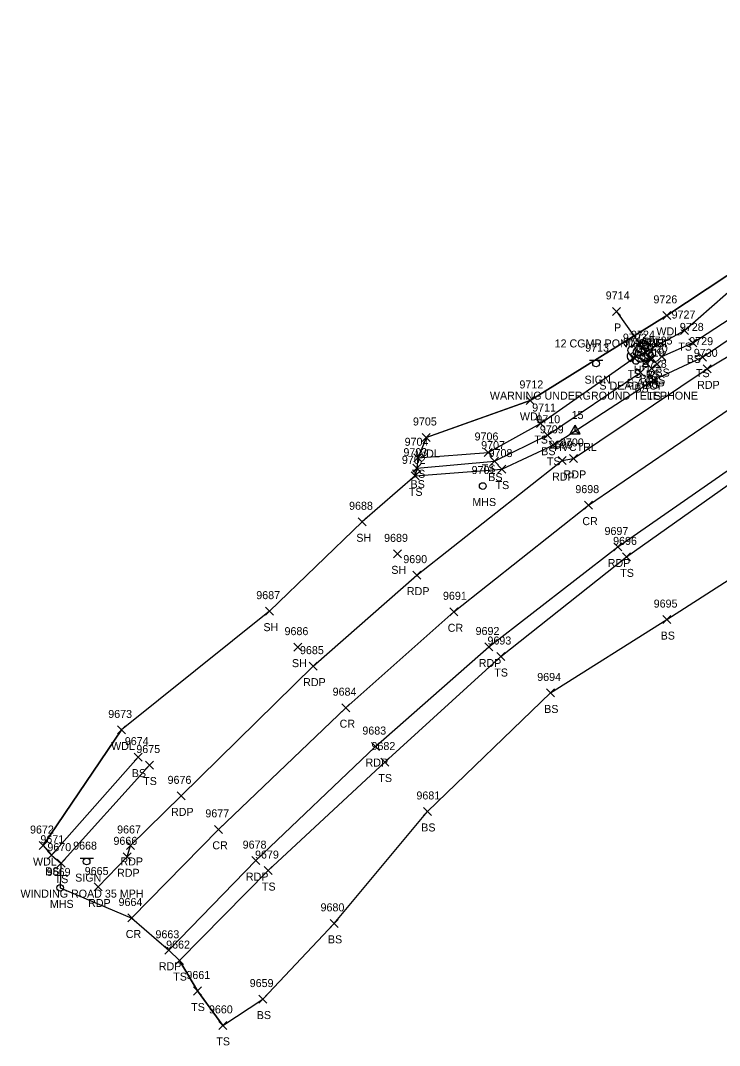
# Model space of a CAD drawing. Extents: x 1651685 to 1653558, y 889533 to 891085.
# Drawn here: x 1651685 to 1651859.6, y 889532.8 to 889789.1 of the extents above; entities that cross this region are included whole.
import ezdxf

# ---------------------------------------------------------------- set-up
doc = ezdxf.new("R2010")
doc.units = 0
for name, color, linetype in [('C_A', 7, 'Continuous'), ('C_I', 7, 'Continuous'), ('CPSM', 7, 'Continuous'), ('D_A', 7, 'Continuous'), ('D_C', 7, 'Continuous'), ('D_I', 7, 'Continuous'), ('D_TIC', 7, 'Continuous'), ('DCP', 7, 'Continuous'), ('L_A', 7, 'Continuous'), ('L_C', 7, 'Continuous'), ('L_I', 7, 'Continuous'), ('L_TIC', 7, 'Continuous'), ('LAWA', 7, 'Continuous'), ('LELB', 7, 'Continuous'), ('LSOGP', 7, 'Continuous'), ('LTD', 7, 'Continuous'), ('P_A', 7, 'Continuous'), ('P_I', 7, 'Continuous'), ('P_TIC', 7, 'Continuous'), ('PET', 7, 'Continuous'), ('PRC', 7, 'Continuous'), ('S_A', 7, 'Continuous'), ('S_C', 7, 'Continuous'), ('S_I', 7, 'Continuous'), ('SSGN', 7, 'Continuous'), ('U_A', 7, 'Continuous'), ('U_I', 7, 'Continuous'), ('USMH', 7, 'Continuous')]:
    doc.layers.add(name, color=color, linetype=linetype)

msp = doc.modelspace()

# ---------------------------------------------------------------- linework, layer by layer
at = {"layer": 'CPSM'}
for p, q in [((1651822.33, 889685.73), (1651823.58, 889687.9)), ((1651824.83, 889685.73), (1651823.58, 889687.9)), ((1651823.58, 889686.45), (1651823.58, 889687.9)), ((1651822.33, 889685.73), (1651823.58, 889686.45)), ((1651822.33, 889685.73), (1651824.83, 889685.73)), ((1651823.58, 889686.45), (1651823.58, 889686.45)), ((1651823.58, 889686.45), (1651824.83, 889685.73))]:
    msp.add_line(p, q, dxfattribs=at)
at = {"layer": 'D_TIC'}
for points in [[(1651832.89, 889715.33), (1651834.89, 889717.33)], [(1651834.89, 889715.33), (1651832.89, 889717.33)], [(1651841.32, 889703.45), (1651843.32, 889705.45)], [(1651843.32, 889703.45), (1651841.32, 889705.45)]]:
    msp.add_lwpolyline(points, dxfattribs=at)
at = {"layer": 'DCP'}
msp.add_lwpolyline([(1651833.89, 889716.33), (1651842.32, 889704.45)], dxfattribs=at)
at = {"layer": 'L_TIC'}
for points in [[(1651845.44, 889714.35), (1651847.44, 889716.35)], [(1651847.44, 889714.35), (1651845.44, 889716.35)], [(1651849.92, 889710.55), (1651851.92, 889712.55)], [(1651851.92, 889710.55), (1651849.92, 889712.55)], [(1651851.98, 889707.46), (1651853.98, 889709.46)], [(1651853.98, 889707.46), (1651851.98, 889709.46)], [(1651837.28, 889703.72), (1651839.28, 889705.72)], [(1651839.28, 889703.72), (1651837.28, 889705.72)], [(1651841.79, 889703.58), (1651843.79, 889705.58)], [(1651843.79, 889703.58), (1651841.79, 889705.58)], [(1651844.19, 889704.05), (1651846.19, 889706.05)], [(1651846.19, 889704.05), (1651844.19, 889706.05)], [(1651854.35, 889703.9), (1651856.35, 889705.9)], [(1651856.35, 889703.9), (1651854.35, 889705.9)], [(1651840.26, 889702.55), (1651842.26, 889704.55)], [(1651842.26, 889702.55), (1651840.26, 889704.55)], [(1651840.26, 889702.55), (1651842.26, 889704.55)], [(1651842.26, 889702.55), (1651840.26, 889704.55)], [(1651841.6, 889701.06), (1651843.6, 889703.06)], [(1651843.6, 889701.06), (1651841.6, 889703.06)], [(1651841.6, 889701.06), (1651843.6, 889703.06)], [(1651843.6, 889701.06), (1651841.6, 889703.06)], [(1651843.08, 889702.13), (1651845.08, 889704.13)], [(1651845.08, 889702.13), (1651843.08, 889704.13)], [(1651838.92, 889700.07), (1651840.92, 889702.07)], [(1651840.92, 889700.07), (1651838.92, 889702.07)], [(1651842.19, 889698.23), (1651844.19, 889700.23)], [(1651844.19, 889698.23), (1651842.19, 889700.23)], [(1651811.33, 889693.08), (1651813.33, 889695.08)], [(1651813.33, 889693.08), (1651811.33, 889695.08)], [(1651813.94, 889687.3), (1651815.94, 889689.3)], [(1651815.94, 889687.3), (1651813.94, 889689.3)], [(1651785.37, 889683.82), (1651787.37, 889685.82)], [(1651787.37, 889683.82), (1651785.37, 889685.82)], [(1651815.65, 889684.38), (1651817.65, 889686.38)], [(1651817.65, 889684.38), (1651815.65, 889686.38)], [(1651800.82, 889680.07), (1651802.82, 889682.07)], [(1651802.82, 889680.07), (1651800.82, 889682.07)], [(1651817.09, 889681.86), (1651819.09, 889683.86)], [(1651819.09, 889681.86), (1651817.09, 889683.86)], [(1651783.29, 889678.75), (1651785.29, 889680.75)], [(1651785.29, 889678.75), (1651783.29, 889680.75)], [(1651802.41, 889677.92), (1651804.41, 889679.92)], [(1651804.41, 889677.92), (1651802.41, 889679.92)], [(1651782.99, 889676.15), (1651784.99, 889678.15)], [(1651784.99, 889676.15), (1651782.99, 889678.15)], [(1651804.26, 889675.92), (1651806.26, 889677.92)], [(1651806.26, 889675.92), (1651804.26, 889677.92)], [(1651782.6, 889674.23), (1651784.6, 889676.23)], [(1651784.6, 889674.23), (1651782.6, 889676.23)], [(1651769.38, 889662.75), (1651771.38, 889664.75)], [(1651771.38, 889662.75), (1651769.38, 889664.75)], [(1651778.14, 889654.73), (1651780.14, 889656.73)], [(1651780.14, 889654.73), (1651778.14, 889656.73)], [(1651835.41, 889653.97), (1651837.41, 889655.97)], [(1651837.41, 889653.97), (1651835.41, 889655.97)], [(1651746.19, 889640.41), (1651748.19, 889642.41)], [(1651748.19, 889640.41), (1651746.19, 889642.41)], [(1651845.48, 889638.3), (1651847.48, 889640.3)], [(1651847.48, 889638.3), (1651845.48, 889640.3)], [(1651753.3, 889631.41), (1651755.3, 889633.41)], [(1651755.3, 889631.41), (1651753.3, 889633.41)], [(1651803.95, 889629.07), (1651805.95, 889631.07)], [(1651805.95, 889629.07), (1651803.95, 889631.07)], [(1651816.38, 889619.96), (1651818.38, 889621.96)], [(1651818.38, 889619.96), (1651816.38, 889621.96)], [(1651709.2, 889610.71), (1651711.2, 889612.71)], [(1651711.2, 889610.71), (1651709.2, 889612.71)], [(1651713.33, 889603.92), (1651715.33, 889605.92)], [(1651715.33, 889603.92), (1651713.33, 889605.92)], [(1651716.21, 889601.94), (1651718.21, 889603.94)], [(1651718.21, 889601.94), (1651716.21, 889603.94)], [(1651774.98, 889602.69), (1651776.98, 889604.69)], [(1651776.98, 889602.69), (1651774.98, 889604.69)], [(1651785.64, 889590.34), (1651787.64, 889592.34)], [(1651787.64, 889590.34), (1651785.64, 889592.34)], [(1651689.66, 889581.82), (1651691.66, 889583.82)], [(1651691.66, 889581.82), (1651689.66, 889583.82)], [(1651691.68, 889579.4), (1651693.68, 889581.4)], [(1651693.68, 889579.4), (1651691.68, 889581.4)], [(1651694.09, 889577.42), (1651696.09, 889579.42)], [(1651696.09, 889577.42), (1651694.09, 889579.42)], [(1651745.88, 889575.56), (1651747.88, 889577.56)], [(1651747.88, 889575.56), (1651745.88, 889577.56)], [(1651762.34, 889562.37), (1651764.34, 889564.37)], [(1651764.34, 889562.37), (1651762.34, 889564.37)], [(1651723.72, 889553.06), (1651725.72, 889555.06)], [(1651725.72, 889553.06), (1651723.72, 889555.06)], [(1651728.21, 889545.46), (1651730.21, 889547.46)], [(1651730.21, 889545.46), (1651728.21, 889547.46)], [(1651744.55, 889543.44), (1651746.55, 889545.44)], [(1651746.55, 889543.44), (1651744.55, 889545.44)], [(1651734.5, 889536.87), (1651736.5, 889538.87)], [(1651736.5, 889536.87), (1651734.5, 889538.87)]]:
    msp.add_lwpolyline(points, dxfattribs=at)
at = {"layer": 'LAWA'}
for points in [[(1651786.37, 889684.82), (1651812.33, 889694.08), (1651846.44, 889715.35), (1651881.58, 889738.54), (1651911.24, 889756.58), (1651953.91, 889775.98), (1651985.79, 889786.86)], [(1651690.66, 889582.82), (1651710.2, 889611.71)]]:
    msp.add_lwpolyline(points, dxfattribs=at)
at = {"layer": 'LELB'}
for points in [[(1651783.6, 889675.23), (1651805.26, 889676.92), (1651818.09, 889682.86), (1651843.19, 889699.23), (1651855.35, 889704.9), (1651888.23, 889726.95), (1651920.63, 889744.86), (1651960.2, 889763.86), (1651990.86, 889775.67), (1652032.94, 889794.22), (1652064, 889805.11), (1652064.62, 889808.53), (1652063.28, 889810.56), (1652051.23, 889809.28), (1652039.29, 889812.4)], [(1651845.19, 889705.05), (1651852.98, 889708.46), (1651886.2, 889730.12), (1651918.71, 889747.83), (1651956.73, 889770.8), (1651985.79, 889786.86), (1652029.06, 889802.11), (1652062.87, 889807.04)], [(1651784.29, 889679.75), (1651801.82, 889681.07), (1651814.94, 889688.3), (1651838.28, 889704.72), (1651850.92, 889711.55), (1651881.58, 889738.54)], [(1651842.6, 889702.06), (1651844.08, 889703.13), (1651842.79, 889704.58), (1651841.26, 889703.55)], [(1651842.6, 889702.06), (1651841.26, 889703.55)], [(1651783.99, 889677.15), (1651803.41, 889678.92), (1651816.65, 889685.38), (1651839.92, 889701.07)], [(1651735.5, 889537.87), (1651729.21, 889546.46), (1651724.72, 889554.06), (1651746.88, 889576.56), (1651775.98, 889603.69), (1651804.95, 889630.07), (1651836.41, 889654.97), (1651869.76, 889678.65), (1651890.05, 889689.78)], [(1651745.55, 889544.44), (1651763.34, 889563.37), (1651786.64, 889591.34), (1651817.38, 889620.96), (1651846.48, 889639.3)], [(1651692.68, 889580.4), (1651714.33, 889604.92)], [(1651695.09, 889578.42), (1651717.21, 889602.94)]]:
    msp.add_lwpolyline(points, dxfattribs=at)
at = {"layer": 'LSOGP'}
msp.add_lwpolyline([(1651881.58, 889738.53), (1651846.44, 889715.35), (1651812.33, 889694.08), (1651786.38, 889684.82), (1651784.29, 889679.75), (1651783.98, 889677.15), (1651783.6, 889675.23), (1651770.37, 889663.74), (1651747.19, 889641.41), (1651710.19, 889611.71), (1651690.66, 889582.82), (1651692.68, 889580.4), (1651695.08, 889578.42), (1651694.88, 889572.22), (1651712.82, 889564.7), (1651722.05, 889556.64), (1651724.72, 889554.06), (1651729.21, 889546.46), (1651735.5, 889537.87), (1651745.56, 889544.44), (1651763.33, 889563.37), (1651786.64, 889591.33), (1651817.38, 889620.96), (1651846.48, 889639.3), (1651872.04, 889655.76)], dxfattribs=at)
at = {"layer": 'LTD'}
for p, q in [((1651838.75, 889705.79), (1651838.75, 889705.79)), ((1651838.75, 889705.79), (1651838.75, 889705.79)), ((1651840.79, 889706.52), (1651840.79, 889706.52)), ((1651840.79, 889706.52), (1651840.79, 889706.52))]:
    msp.add_line(p, q, dxfattribs=at)
for centre in [(1651838.8, 889707.23), (1651840.84, 889707.95)]:
    msp.add_arc(centre, 1.05, 335.5272, 180.9563, dxfattribs=at)
for centre, major_axis, ratio, start_param, end_param in [((1651837.96, 889706.46), (1.21, -0.51), 0.895232, 1.570796, 4.712389), ((1651840, 889707.19), (1.21, -0.51), 0.895232, 1.570796, 4.712389), ((1651839.79, 889706.38), (-1.14, -0.48), 0.949671, 1.570796, 4.712389), ((1651840.58, 889706.98), (-0.208, -0.792), 0.645439, 3.141593, 6.283185), ((1651841.83, 889707.1), (-1.14, -0.48), 0.949671, 1.570796, 4.712389), ((1651837.67, 889705.08), (0.58, -1.04), 0.959034, 3.141593, 6.283185), ((1651838.29, 889705.04), (-0.625, -0.083), 0.423636, 0, 3.141593), ((1651838.54, 889706.25), (-0.208, -0.792), 0.645439, 3.141593, 6.283185), ((1651839.71, 889705.81), (0.58, -1.04), 0.959034, 3.141593, 6.283185), ((1651839.25, 889705.63), (-0.5, 0.667), 0.989748, 3.141593, 6.283185), ((1651839.75, 889704.96), (-1.09, 0.79), 0.841452, 1.570796, 4.712389), ((1651840.79, 889705.02), (0.26, 1.06), 0.942809, 1.570796, 4.712389), ((1651840.33, 889705.77), (-0.625, -0.083), 0.423636, 0, 3.141593), ((1651841.29, 889706.35), (-0.5, 0.667), 0.989748, 3.141593, 6.283185), ((1651841.79, 889705.69), (-1.09, 0.79), 0.841452, 1.570796, 4.712389), ((1651838.75, 889704.29), (0.26, 1.06), 0.942809, 1.570796, 4.712389)]:
    msp.add_ellipse(centre, major_axis=major_axis, ratio=ratio, start_param=start_param, end_param=end_param, dxfattribs=at)
at = {"layer": 'P_TIC'}
for points in [[(1651855.55, 889700.98), (1651857.55, 889702.98)], [(1651857.55, 889700.98), (1651855.55, 889702.98)], [(1651819.32, 889678.04), (1651821.32, 889680.04)], [(1651821.32, 889678.04), (1651819.32, 889680.04)], [(1651822.18, 889678.59), (1651824.18, 889680.59)], [(1651824.18, 889678.59), (1651822.18, 889680.59)], [(1651825.92, 889666.91), (1651827.92, 889668.91)], [(1651827.92, 889666.91), (1651825.92, 889668.91)], [(1651833.2, 889656.45), (1651835.2, 889658.45)], [(1651835.2, 889656.45), (1651833.2, 889658.45)], [(1651783.02, 889649.41), (1651785.02, 889651.41)], [(1651785.02, 889649.41), (1651783.02, 889651.41)], [(1651792.27, 889640.25), (1651794.27, 889642.25)], [(1651794.27, 889640.25), (1651792.27, 889642.25)], [(1651800.99, 889631.45), (1651802.99, 889633.45)], [(1651802.99, 889631.45), (1651800.99, 889633.45)], [(1651757.1, 889626.66), (1651759.1, 889628.66)], [(1651759.1, 889626.66), (1651757.1, 889628.66)], [(1651765.27, 889616.28), (1651767.27, 889618.28)], [(1651767.27, 889616.28), (1651765.27, 889618.28)], [(1651772.7, 889606.56), (1651774.7, 889608.56)], [(1651774.7, 889606.56), (1651772.7, 889608.56)], [(1651724.08, 889594.24), (1651726.08, 889596.24)], [(1651726.08, 889594.24), (1651724.08, 889596.24)], [(1651733.46, 889585.87), (1651735.46, 889587.87)], [(1651735.46, 889585.87), (1651733.46, 889587.87)], [(1651711.47, 889581.84), (1651713.47, 889583.84)], [(1651713.47, 889581.84), (1651711.47, 889583.84)], [(1651710.6, 889579), (1651712.6, 889581)], [(1651712.6, 889579), (1651710.6, 889581)], [(1651742.79, 889578.05), (1651744.79, 889580.05)], [(1651744.79, 889578.05), (1651742.79, 889580.05)], [(1651703.37, 889571.46), (1651705.37, 889573.46)], [(1651705.37, 889571.46), (1651703.37, 889573.46)], [(1651711.82, 889563.71), (1651713.82, 889565.71)], [(1651713.82, 889563.71), (1651711.82, 889565.71)], [(1651721.05, 889555.64), (1651723.05, 889557.64)], [(1651723.05, 889555.64), (1651721.05, 889557.64)]]:
    msp.add_lwpolyline(points, dxfattribs=at)
at = {"layer": 'PET'}
for points in [[(1651722.05, 889556.64), (1651743.79, 889579.05), (1651773.7, 889607.56), (1651801.99, 889632.45), (1651834.2, 889657.45), (1651868.37, 889681.24), (1651890.21, 889694.54), (1651910.42, 889705.67), (1651932.43, 889717.43), (1651971.73, 889735.64), (1652001.72, 889748.76), (1652035.56, 889763.08), (1652038.22, 889762.81), (1652052.59, 889768.76), (1652053.52, 889770.62), (1652076.54, 889779.88), (1652117.63, 889796.48), (1652147.54, 889808.21), (1652195.16, 889826.81), (1652233.48, 889842.54), (1652271.73, 889857.62), (1652310.07, 889873.86), (1652345.02, 889890.88)], [(1651704.37, 889572.46), (1651711.6, 889580), (1651712.47, 889582.84), (1651725.08, 889595.24), (1651758.1, 889627.66), (1651784.02, 889650.41), (1651820.32, 889679.04), (1651823.18, 889679.59), (1651856.55, 889701.98), (1651890.95, 889722.59), (1651906.13, 889732.21), (1651930.88, 889744.68), (1651940.4, 889747.37), (1651962.5, 889757.26), (1651993.09, 889770.39), (1652035.55, 889788.28)]]:
    msp.add_lwpolyline(points, dxfattribs=at)
at = {"layer": 'PRC'}
msp.add_lwpolyline([(1651712.82, 889564.71), (1651734.46, 889586.87), (1651766.27, 889617.28), (1651793.27, 889641.25), (1651826.92, 889667.91), (1651862.27, 889692.04), (1651896.77, 889712.72), (1651926.87, 889728.69), (1651966.67, 889747.09), (1651996.7, 889760.13), (1652040.05, 889778.15), (1652073.02, 889791.69), (1652113.32, 889807.56), (1652142.44, 889819.25), (1652190.37, 889838.24), (1652228.92, 889853.82), (1652266.92, 889869.48), (1652304.43, 889885.84), (1652339.13, 889902.36), (1652374.76, 889921.45)], dxfattribs=at)
at = {"layer": 'SSGN'}
for p, q in [((1651827.13, 889704.14), (1651830.46, 889704.14)), ((1651828.77, 889703.3), (1651828.77, 889703.3)), ((1651699.85, 889579.66), (1651703.18, 889579.66)), ((1651701.5, 889578.82), (1651701.5, 889578.82))]:
    msp.add_line(p, q, dxfattribs=at)
for centre in [(1651828.77, 889703.3), (1651701.5, 889578.82)]:
    msp.add_circle(centre, 0.833, dxfattribs=at)
at = {"layer": 'USMH'}
for p, q in [((1651800.46, 889672.69), (1651800.46, 889672.69)), ((1651801.29, 889672.69), (1651801.29, 889672.69)), ((1651694.88, 889572.23), (1651694.88, 889572.23)), ((1651695.72, 889572.23), (1651695.72, 889572.23))]:
    msp.add_line(p, q, dxfattribs=at)
for centre in [(1651800.46, 889672.69), (1651694.88, 889572.23)]:
    msp.add_circle(centre, 0.833, dxfattribs=at)

# ---------------------------------------------------------------- texts
at = {"layer": 'C_A'}
msp.add_text('HVCTRL', height=2, dxfattribs=at).set_placement((1651818.27, 889681.45))
at = {"layer": 'C_I'}
msp.add_text('15', height=2, dxfattribs=at).set_placement((1651822.68, 889689.45))
at = {"layer": 'D_A'}
for p in [(1651833.27, 889711.33), (1651841.7, 889699.45)]:
    msp.add_text('P', height=2, dxfattribs=at).set_placement(p)
at = {"layer": 'D_C'}
msp.add_text('12 CGMP POND INLET', height=2, dxfattribs=at).set_placement((1651818.43, 889707.33))
at = {"layer": 'D_I'}
for s, p in [('9714', (1651831.2, 889719.33)), ('9715', (1651839.63, 889707.45))]:
    msp.add_text(s, height=2, dxfattribs=at).set_placement(p)
at = {"layer": 'L_A'}
for s, p in [('WDL', (1651843.85, 889710.35)), ('TS', (1651849.33, 889706.55)), ('BS', (1651851.42, 889703.46)), ('H', (1651838.18, 889700.79)), ('H', (1651840.22, 889701.52)), ('TS', (1651836.69, 889699.72)), ('BS', (1651839.7, 889698.55)), ('BS', (1651839.7, 889698.55)), ('BS', (1651841.23, 889699.58)), ('BS', (1651842.52, 889698.13)), ('BS', (1651843.63, 889700.05)), ('TS', (1651853.76, 889699.9)), ('BS', (1651838.36, 889696.07)), ('BS', (1651841.04, 889697.06)), ('BS', (1651841.04, 889697.06)), ('TS', (1651841.6, 889694.23)), ('WDL', (1651809.75, 889689.08)), ('TS', (1651813.35, 889683.3)), ('WDL', (1651783.79, 889679.82)), ('BS', (1651815.09, 889680.38)), ('TS', (1651816.5, 889677.86)), ('TS', (1651782.7, 889674.75)), ('TS', (1651800.23, 889676.07)), ('BS', (1651782.43, 889672.15)), ('BS', (1651801.85, 889673.92)), ('TS', (1651782.01, 889670.23)), ('TS', (1651803.67, 889671.92)), ('SH', (1651768.87, 889658.75)), ('SH', (1651777.62, 889650.73)), ('TS', (1651834.82, 889649.97)), ('SH', (1651745.68, 889636.41)), ('BS', (1651844.92, 889634.3)), ('SH', (1651752.79, 889627.41)), ('TS', (1651803.36, 889625.07)), ('BS', (1651815.82, 889615.96)), ('WDL', (1651707.61, 889606.71)), ('BS', (1651712.77, 889599.92)), ('TS', (1651715.62, 889597.94)), ('TS', (1651774.39, 889598.69)), ('BS', (1651785.09, 889586.34)), ('WDL', (1651688.08, 889577.82)), ('BS', (1651691.12, 889575.4)), ('TS', (1651693.5, 889573.42)), ('TS', (1651745.29, 889571.56)), ('BS', (1651761.78, 889558.37)), ('TS', (1651723.13, 889549.06)), ('TS', (1651727.62, 889541.46)), ('BS', (1651744, 889539.44)), ('TS', (1651733.9, 889532.87))]:
    msp.add_text(s, height=2, dxfattribs=at).set_placement(p)
at = {"layer": 'L_C'}
for s, p in [('S DEAD POP', (1651829.61, 889696.79)), ('S ASH', (1651836.41, 889697.52))]:
    msp.add_text(s, height=2, dxfattribs=at).set_placement(p)
at = {"layer": 'L_I'}
for s, p in [('9726', (1651843.12, 889718.35)), ('9727', (1651847.66, 889714.55)), ('9728', (1651849.72, 889711.46)), ('9723', (1651835.49, 889708.79)), ('9724', (1651837.53, 889709.52)), ('9725', (1651841.93, 889708.05)), ('9716', (1651835.54, 889707.72)), ('9722', (1651838, 889706.55)), ('9722', (1651838, 889706.55)), ('9721', (1651840.1, 889707.58)), ('9720', (1651840.73, 889706.13)), ('9729', (1651852.08, 889707.9)), ('9717', (1651837.22, 889704.07)), ('9719', (1651839.9, 889705.06)), ('9719', (1651839.9, 889705.06)), ('9718', (1651840.49, 889702.23)), ('9712', (1651809.64, 889697.08)), ('9711', (1651812.82, 889691.3)), ('9705', (1651783.03, 889687.82)), ('9710', (1651813.87, 889688.38)), ('9709', (1651814.74, 889685.86)), ('9704', (1651780.95, 889682.75)), ('9706', (1651798.43, 889684.07)), ('9703', (1651780.65, 889680.15)), ('9707', (1651800.07, 889681.92)), ('9708', (1651801.93, 889679.92)), ('9702', (1651780.26, 889678.23)), ('9688', (1651767.07, 889666.75)), ('9689', (1651775.82, 889658.73)), ('9696', (1651833.05, 889657.97)), ('9687', (1651743.88, 889644.41)), ('9695', (1651843.18, 889642.3)), ('9686', (1651750.94, 889635.41)), ('9693', (1651801.65, 889633.07)), ('9694', (1651814.08, 889623.96)), ('9673', (1651706.89, 889614.71)), ('9674', (1651711.03, 889607.92)), ('9675', (1651713.91, 889605.94)), ('9682', (1651772.67, 889606.69)), ('9681', (1651783.9, 889594.34)), ('9672', (1651687.35, 889585.82)), ('9671', (1651689.94, 889583.4)), ('9670', (1651691.69, 889581.42)), ('9679', (1651743.57, 889579.56)), ('9680', (1651759.94, 889566.37)), ('9662', (1651721.36, 889557.06)), ('9661', (1651726.42, 889549.46)), ('9659', (1651742.24, 889547.44)), ('9660', (1651732.05, 889540.87))]:
    msp.add_text(s, height=2, dxfattribs=at).set_placement(p)
at = {"layer": 'P_A'}
for s, p in [('RDP', (1651854.04, 889696.98)), ('RDP', (1651817.81, 889674.04)), ('RDP', (1651820.67, 889674.59)), ('CR', (1651825.35, 889662.91)), ('RDP', (1651831.69, 889652.45)), ('RDP', (1651781.51, 889645.41)), ('CR', (1651791.71, 889636.25)), ('RDP', (1651799.47, 889627.45)), ('RDP', (1651755.59, 889622.66)), ('CR', (1651764.7, 889612.28)), ('RDP', (1651771.18, 889602.56)), ('RDP', (1651722.57, 889590.24)), ('CR', (1651732.9, 889581.87)), ('RDP', (1651709.95, 889577.84)), ('RDP', (1651709.09, 889575)), ('RDP', (1651741.28, 889574.05)), ('RDP', (1651701.85, 889567.46)), ('CR', (1651711.26, 889559.71)), ('RDP', (1651719.53, 889551.64))]:
    msp.add_text(s, height=2, dxfattribs=at).set_placement(p)
at = {"layer": 'P_I'}
for s, p in [('9730', (1651853.21, 889704.98)), ('9700', (1651819.76, 889682.59)), ('9699', (1651817.01, 889682.04)), ('9698', (1651823.61, 889670.91)), ('9697', (1651830.9, 889660.45)), ('9690', (1651780.62, 889653.41)), ('9691', (1651790.53, 889644.25)), ('9692', (1651798.68, 889635.45)), ('9685', (1651754.8, 889630.66)), ('9684', (1651762.96, 889620.28)), ('9683', (1651770.39, 889610.56)), ('9676', (1651721.72, 889598.24)), ('9677', (1651731.16, 889589.87)), ('9667', (1651709.11, 889585.84)), ('9666', (1651708.19, 889583)), ('9678', (1651740.48, 889582.05)), ('9665', (1651701.01, 889575.46)), ('9664', (1651709.47, 889567.71)), ('9663', (1651718.69, 889559.64))]:
    msp.add_text(s, height=2, dxfattribs=at).set_placement(p)
at = {"layer": 'S_A'}
for p in [(1651825.91, 889698.28), (1651698.63, 889573.8)]:
    msp.add_text('SIGN', height=2, dxfattribs=at).set_placement(p)
at = {"layer": 'S_C'}
for s, p in [('WARNING UNDERGROUND TELEPHONE', (1651802.25, 889694.28)), ('WINDING ROAD 35 MPH', (1651684.96, 889569.8))]:
    msp.add_text(s, height=2, dxfattribs=at).set_placement(p)
at = {"layer": 'S_I'}
for s, p in [('9713', (1651826.06, 889706.28)), ('9668', (1651698.12, 889581.8))]:
    msp.add_text(s, height=2, dxfattribs=at).set_placement(p)
at = {"layer": 'U_A'}
for p in [(1651797.87, 889667.69), (1651692.3, 889567.23)]:
    msp.add_text('MHS', height=2, dxfattribs=at).set_placement(p)
at = {"layer": 'U_I'}
for s, p in [('9701', (1651797.69, 889675.69)), ('9669', (1651691.52, 889575.23))]:
    msp.add_text(s, height=2, dxfattribs=at).set_placement(p)

doc.saveas('drawing.dxf')
